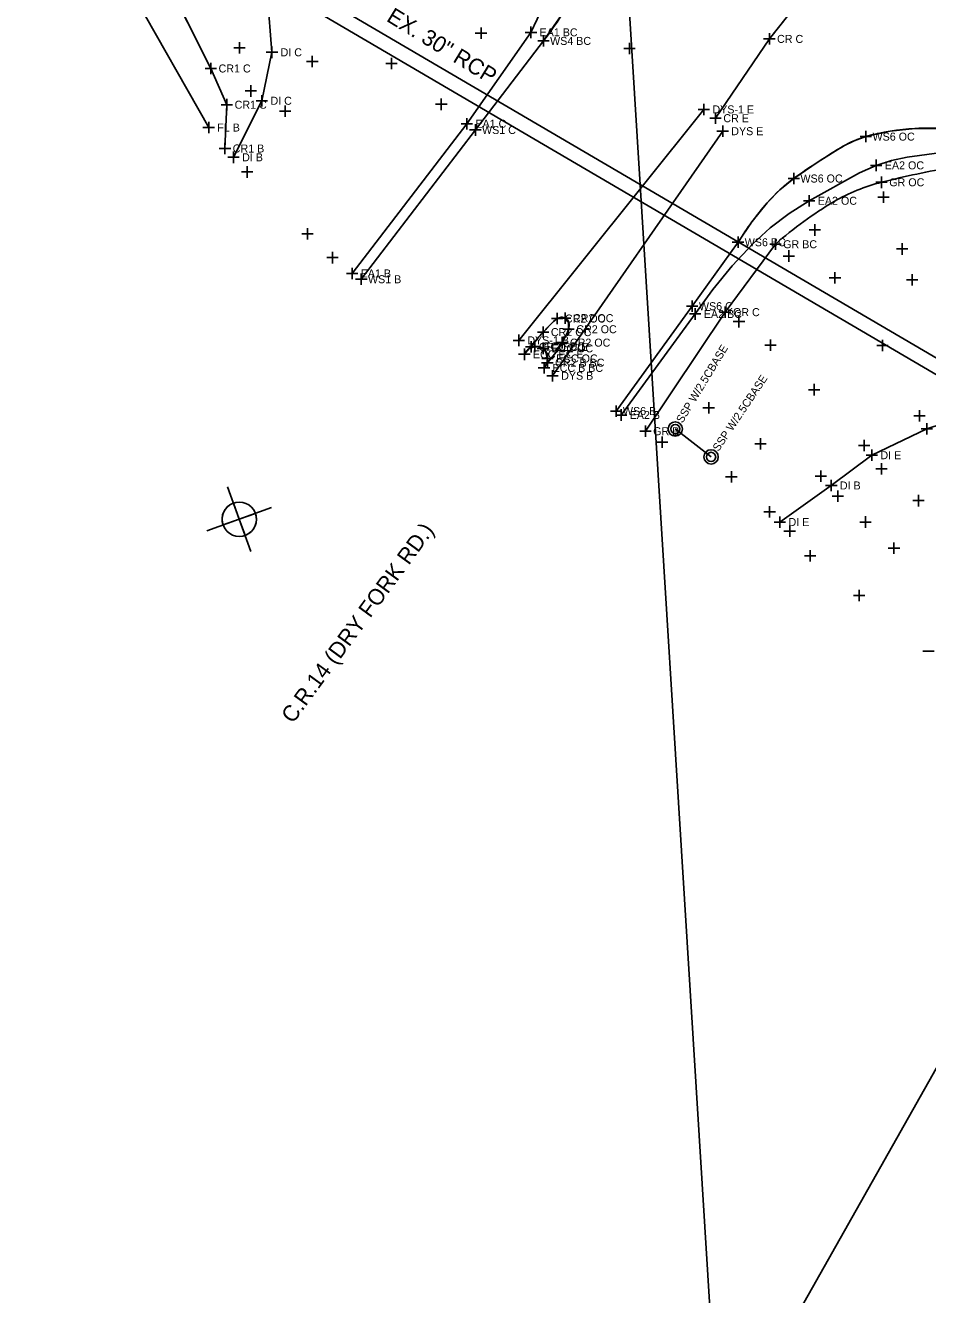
# Model space of a CAD drawing. Extents: x 1324236 to 1326110, y 459090 to 460782.
# Drawn here: x 1324868.3 to 1325026.2, y 459650.5 to 459872.5 of the extents above; entities that cross this region are included whole.
import ezdxf

# ---------------------------------------------------------------- set-up
doc = ezdxf.new("R2010")
doc.units = 0
for name, color, linetype in [('BD_X_Canopy', 7, 'Continuous'), ('DR_X_Ditch', 7, 'Continuous'), ('DR_X_Drive_Pipe', 7, 'Continuous'), ('DR_X_Storm_Sewer', 7, 'Continuous'), ('DT_X_Contour_Minor', 7, 'Continuous'), ('DT_X_Island', 7, 'Continuous'), ('DV_X_Property_Line', 7, 'Continuous'), ('E-RW-ODOT', 7, 'Continuous'), ('GT_Project_Soil_Boring', 7, 'Continuous'), ('PM_X_CL_Double_Solid', 7, 'Continuous'), ('PM_X_Edge_Line', 7, 'Continuous'), ('PM_X_Misc', 7, 'Continuous'), ('PV_X_Shoulder', 7, 'Continuous'), ('RD_X_Text', 7, 'Continuous'), ('RW_X_CL', 7, 'Continuous'), ('RW_X_Esmt_SH', 7, 'Continuous'), ('SN_X_Foundation', 7, 'Continuous'), ('UT_X_Telecom', 7, 'Continuous'), ('VG_X_Flower_Bed', 7, 'Continuous')]:
    doc.layers.add(name, color=color, linetype=linetype)

msp = doc.modelspace()

# ---------------------------------------------------------------- linework, layer by layer
at = {"layer": 'BD_X_Canopy'}
for p, q in [((1324954.64, 459817.45), (1324987.02, 459857.85)), ((1324960.56, 459811.26), (1324990.32, 459854.04))]:
    msp.add_line(p, q, dxfattribs=at)
for points in [[(1325033.14, 459916.69), (1325022.37, 459901.78), (1325012.02, 459887.28), (1324998.48, 459870.18), (1324989.07, 459856.31)], [(1324959.64, 459813.54), (1324961.13, 459815.33), (1324961.13, 459815.33), (1324962.23, 459817.05), (1324962.23, 459817.05), (1324963.09, 459818.72), (1324963.09, 459818.72), (1324963.35, 459819.39), (1324963.35, 459819.39), (1324963.37, 459820.62), (1324963.37, 459820.62), (1324962.77, 459821.33), (1324962.77, 459821.33), (1324962.03, 459821.49), (1324962.03, 459821.49), (1324961.36, 459821.26), (1324961.36, 459821.26), (1324960.74, 459820.75), (1324960.74, 459820.75), (1324958.9, 459818.89), (1324958.9, 459818.89), (1324957.91, 459817.75), (1324957.91, 459817.75), (1324956.8, 459816.3), (1324956.8, 459816.3)]]:
    msp.add_lwpolyline(points, dxfattribs=at)
at = {"layer": 'DR_X_Ditch'}
for points in [[(1324927.09, 459828.14), (1324947.05, 459854.25), (1324958.95, 459869.83), (1324962.07, 459874.27), (1324964.69, 459879.02), (1324964.69, 459879.02), (1324966.48, 459883.2), (1324967.88, 459887.52), (1324968.88, 459891.96), (1324968.88, 459891.96)], [(1324971.69, 459805.08), (1324984.99, 459823.42), (1324993, 459834.61), (1324995.42, 459838.17), (1324998.11, 459841.52), (1324998.11, 459841.52), (1325000.32, 459843.77), (1325002.76, 459845.76), (1325002.76, 459845.76), (1325007.02, 459848.69), (1325011.42, 459851.4), (1325011.42, 459851.4), (1325013.34, 459852.37), (1325015.37, 459853.09), (1325015.37, 459853.09), (1325019.64, 459854.06), (1325023.99, 459854.53), (1325023.99, 459854.53), (1325029.18, 459854.52)], [(1324959.06, 459812.63), (1324959.55, 459813.44), (1324959.55, 459813.44), (1324959.67, 459814.28), (1324959.67, 459814.28), (1324959.4, 459815.4), (1324959.4, 459815.4), (1324958.88, 459816.05), (1324958.88, 459816.05), (1324958.32, 459816.31), (1324958.32, 459816.31), (1324957.45, 459816.38), (1324957.45, 459816.38), (1324956.38, 459815.99), (1324956.38, 459815.99), (1324955.62, 459815.01), (1324955.62, 459815.01)]]:
    msp.add_lwpolyline(points, dxfattribs=at)
for centre, radius, start, end in [((1324964.18, 459817.18), 4.96, 124.6261, 133.9329), ((1324962.1, 459820.19), 1.29, 92.7917, 124.6261), ((1324962.1, 459820.01), 1.48, 63.1066, 92.7917), ((1324962.25, 459820.28), 1.17, 16.6018, 63.1066), ((1324973.77, 459804.91), 20.41, 136.7902, 141.023), ((1324997.15, 459782.96), 52.48, 133.9329, 136.7902), ((1324958.38, 459820.99), 5.22, 334.2458, 342.1532), ((1324961.37, 459820.02), 2.08, 342.1532, 16.6018), ((1324981.13, 459798.96), 29.87, 141.023, 144.5216), ((1324948.72, 459824.47), 15.41, 323.6029, 331.2095), ((1324931.24, 459834.08), 35.36, 331.2095, 334.2458), ((1324945.05, 459827.18), 19.97, 316.922, 323.6029)]:
    msp.add_arc(centre, radius, start, end, dxfattribs=at)
at = {"layer": 'DR_X_Drive_Pipe'}
for p, q in [((1324911.46, 459867.84), (1324910.65, 459878.08)), ((1324909.7, 459859.36), (1324911.46, 459867.84)), ((1324904.74, 459849.47), (1324909.7, 459859.36)), ((1325034.32, 459804.68), (1325026.02, 459801.97)), ((1325026.02, 459801.97), (1325016.41, 459797.36)), ((1325016.41, 459797.36), (1325009.32, 459792.06)), ((1325009.32, 459792.06), (1325000.33, 459785.66))]:
    msp.add_line(p, q, dxfattribs=at)
at = {"layer": 'DR_X_Storm_Sewer'}
for p, q in [((1324954.64, 459817.45), (1324987.02, 459857.85)), ((1324960.56, 459811.26), (1324990.32, 459854.04))]:
    msp.add_line(p, q, dxfattribs=at)
at = {"layer": 'DT_X_Contour_Minor'}
msp.add_line((1324982.02, 459801.95), (1324988.29, 459797.06), dxfattribs=at)
for centre in [(1324982.02, 459801.95), (1324988.29, 459797.06)]:
    msp.add_circle(centre, 0.8, dxfattribs=at)
at = {"layer": 'DT_X_Island'}
for p, q in [((1325012.02, 459887.28), (1324998.48, 459870.18)), ((1324900.76, 459865.01), (1324892.6, 459881.25)), ((1324998.48, 459870.18), (1324989.07, 459856.31)), ((1324903.57, 459858.67), (1324900.76, 459865.01)), ((1324903.24, 459851.01), (1324903.57, 459858.67))]:
    msp.add_line(p, q, dxfattribs=at)
msp.add_lwpolyline([(1324903.24, 459851.01), (1324903.57, 459858.67), (1324900.76, 459865.01), (1324892.6, 459881.25), (1324884.84, 459894.47), (1324875.27, 459911.41), (1324865.42, 459926.97), (1324851.91, 459949.8), (1324844.34, 459963.96), (1324828.37, 459990.29), (1324813.52, 460017.04), (1324795.99, 460045.7), (1324776.37, 460074.14), (1324759.04, 460097.56), (1324741.91, 460121.91), (1324723.89, 460144.49), (1324705.48, 460167.97), (1324684.34, 460188.18), (1324670.72, 460214.69), (1324651.5, 460238.08), (1324632.66, 460258.86), (1324612.54, 460278.22)], dxfattribs=at)
at = {"layer": 'DV_X_Property_Line'}
for p, q in [((1324956.78, 459870.33), (1324956.78, 459872.33)), ((1324955.78, 459871.33), (1324957.78, 459871.33)), ((1324944.55, 459855.34), (1324946.55, 459855.34)), ((1324945.55, 459854.34), (1324945.55, 459856.34)), ((1325016.18, 459848.06), (1325018.18, 459848.06)), ((1325017.18, 459847.06), (1325017.18, 459849.06)), ((1325004.45, 459841.87), (1325006.45, 459841.87)), ((1325005.45, 459840.87), (1325005.45, 459842.87)), ((1324925.49, 459828.15), (1324925.49, 459830.15)), ((1324924.49, 459829.15), (1324926.49, 459829.15)), ((1324984.52, 459822.06), (1324986.52, 459822.06)), ((1324985.52, 459821.06), (1324985.52, 459823.06)), ((1324957.45, 459815.38), (1324957.45, 459817.38)), ((1324958.88, 459815.05), (1324958.88, 459817.05)), ((1324954.62, 459815.01), (1324956.62, 459815.01)), ((1324955.62, 459814.01), (1324955.62, 459816.01)), ((1324956.45, 459816.38), (1324958.45, 459816.38)), ((1324957.88, 459816.05), (1324959.88, 459816.05)), ((1324959.67, 459813.28), (1324959.67, 459815.28)), ((1324958.06, 459812.63), (1324960.06, 459812.63)), ((1324958.67, 459814.28), (1324960.67, 459814.28)), ((1324959.06, 459811.63), (1324959.06, 459813.63)), ((1324971.54, 459804.39), (1324973.54, 459804.39)), ((1324972.54, 459803.39), (1324972.54, 459805.39))]:
    msp.add_line(p, q, dxfattribs=at)
for centre in [(1324982.02, 459801.95), (1324988.29, 459797.06)]:
    msp.add_circle(centre, 1.25, dxfattribs=at)
for centre, radius, start, end in [((1324957.78, 459814.13), 2.33, 126.9602, 157.8828), ((1324957.56, 459814.42), 1.96, 93.2286, 126.9602), ((1324957.62, 459813.32), 3.06, 76.838, 93.2286), ((1324957.98, 459814.85), 1.5, 53.3002, 76.838), ((1324957.88, 459814.72), 1.66, 24.2708, 53.3002), ((1324956.47, 459814.08), 3.21, 3.5121, 24.2708), ((1324957.12, 459814.34), 2.59, 318.6278, 339.7188), ((1324957.63, 459814.15), 2.04, 339.7188, 3.5121)]:
    msp.add_arc(centre, radius, start, end, dxfattribs=at)
at = {"layer": 'E-RW-ODOT'}
for p, q in [((1324989.68, 459622.77), (1324967.69, 459977.08)), ((1324989.68, 459622.77), (1324967.69, 459977.08)), ((1325119.34, 459852.69), (1324989.68, 459622.77))]:
    msp.add_line(p, q, dxfattribs=at)
at = {"layer": 'GT_Project_Soil_Boring'}
for p, q in [((1324905.74, 459786.16), (1324903.71, 459791.81)), ((1324904.73, 459788.99), (1324905.74, 459786.16)), ((1324905.74, 459786.16), (1324911.39, 459788.19)), ((1324905.74, 459786.16), (1324900.09, 459784.14)), ((1324905.74, 459786.16), (1324902.91, 459785.15)), ((1324905.74, 459786.16), (1324908.56, 459787.18)), ((1324905.74, 459786.16), (1324907.76, 459780.51)), ((1324906.75, 459783.34), (1324905.74, 459786.16))]:
    msp.add_line(p, q, dxfattribs=at)
msp.add_circle((1324905.74, 459786.16), 3, dxfattribs=at)
for start, end in [(109.7344, 199.7344), (289.7344, 19.7344)]:
    msp.add_arc((1324905.74, 459786.16), 3, start, end, dxfattribs=at)
at = {"layer": 'PM_X_CL_Double_Solid'}
msp.add_line((1324900.39, 459854.68), (1324887.39, 459877.62), dxfattribs=at)
at = {"layer": 'PM_X_Edge_Line'}
for p, q in [((1324947.05, 459854.25), (1324958.95, 459869.83)), ((1324927.09, 459828.14), (1324947.05, 459854.25)), ((1324984.99, 459823.42), (1324993, 459834.61)), ((1324971.69, 459805.08), (1324984.99, 459823.42))]:
    msp.add_line(p, q, dxfattribs=at)
for centre, radius, start, end in [((1324919.7, 459900.73), 49.95, 321.7901, 334.235), ((1325025.8, 459817.1), 37.47, 92.769, 106.1642), ((1325026.54, 459801.82), 52.77, 81.4885, 92.769), ((1325020.26, 459836.2), 17.59, 106.1642, 120.1668), ((1325062.86, 459762.92), 102.35, 120.1668, 125.9597), ((1325019.22, 459823.06), 28.04, 125.9597, 138.8315), ((1325037.58, 459807.01), 52.42, 138.8315, 148.2369)]:
    msp.add_arc(centre, radius, start, end, dxfattribs=at)
at = {"layer": 'PM_X_Misc'}
for p, q in [((1324990.77, 459822.38), (1324999.54, 459834.26)), ((1324976.8, 459801.55), (1324990.77, 459822.38))]:
    msp.add_line(p, q, dxfattribs=at)
for centre, radius, start, end in [((1325064.42, 459660.73), 190.1, 100.2725, 104.1003), ((1325025.86, 459814.21), 31.86, 104.1003, 120.2848), ((1325041.9, 459786.75), 63.65, 120.2848, 131.7154)]:
    msp.add_arc(centre, radius, start, end, dxfattribs=at)
at = {"layer": 'PV_X_Shoulder'}
for points in [[(1324925.49, 459829.15), (1324945.55, 459855.34), (1324956.78, 459871.33), (1324958.97, 459875.95), (1324960.87, 459880.7), (1324960.87, 459880.7), (1324962.58, 459885.86), (1324963.96, 459891.11), (1324963.96, 459891.11), (1324983.54, 459896), (1324987.7, 459905.44), (1325002.15, 459921.48), (1325006.99, 459922.03), (1325011.69, 459923.28), (1325011.69, 459923.28), (1325015.28, 459924.75), (1325018.67, 459926.62), (1325021.83, 459928.86), (1325021.83, 459928.86), (1325032.72, 459941.95), (1325043.21, 459955.43)], [(1324972.54, 459804.39), (1324985.52, 459822.06), (1324988.59, 459826.37), (1324991.96, 459830.46), (1324995.58, 459834.32), (1324995.58, 459834.32), (1324998.65, 459837.12), (1325001.95, 459839.64), (1325005.45, 459841.87), (1325005.45, 459841.87), (1325014.25, 459846.73), (1325014.25, 459846.73), (1325017.18, 459848.06), (1325017.18, 459848.06), (1325019.85, 459848.92), (1325022.6, 459849.51), (1325022.6, 459849.51), (1325028.21, 459850.26)]]:
    msp.add_lwpolyline(points, dxfattribs=at)
at = {"layer": 'RW_X_CL'}
for p, q in [((1324948.04, 459870.17), (1324948.04, 459872.17)), ((1324947.04, 459871.17), (1324949.04, 459871.17)), ((1324958.95, 459868.83), (1324958.95, 459870.83)), ((1324997.48, 459870.18), (1324999.48, 459870.18)), ((1324998.48, 459869.18), (1324998.48, 459871.18)), ((1324904.8, 459868.64), (1324906.8, 459868.64)), ((1324905.8, 459867.64), (1324905.8, 459869.64)), ((1324957.95, 459869.83), (1324959.95, 459869.83)), ((1324973.03, 459868.5), (1324975.03, 459868.5)), ((1324974.03, 459867.5), (1324974.03, 459869.5)), ((1324900.76, 459864.01), (1324900.76, 459866.01)), ((1324917.52, 459866.24), (1324919.52, 459866.24)), ((1324918.52, 459865.24), (1324918.52, 459867.24)), ((1324931.37, 459865.87), (1324933.37, 459865.87)), ((1324932.37, 459864.87), (1324932.37, 459866.87)), ((1324899.76, 459865.01), (1324901.76, 459865.01)), ((1324906.78, 459861.07), (1324908.78, 459861.07)), ((1324907.78, 459860.07), (1324907.78, 459862.07)), ((1324903.57, 459857.67), (1324903.57, 459859.67)), ((1324941.09, 459857.74), (1324941.09, 459859.74)), ((1324987.02, 459856.85), (1324987.02, 459858.85)), ((1324902.57, 459858.67), (1324904.57, 459858.67)), ((1324912.77, 459857.53), (1324914.77, 459857.53)), ((1324913.77, 459856.53), (1324913.77, 459858.53)), ((1324940.09, 459858.74), (1324942.09, 459858.74)), ((1324986.02, 459857.85), (1324988.02, 459857.85)), ((1324989.07, 459855.31), (1324989.07, 459857.31)), ((1324947.05, 459853.25), (1324947.05, 459855.25)), ((1324988.07, 459856.31), (1324990.07, 459856.31)), ((1324990.32, 459853.04), (1324990.32, 459855.04)), ((1324946.05, 459854.25), (1324948.05, 459854.25)), ((1324989.32, 459854.04), (1324991.32, 459854.04)), ((1325014.37, 459853.09), (1325016.37, 459853.09)), ((1325015.37, 459852.09), (1325015.37, 459854.09)), ((1324902.24, 459851.01), (1324904.24, 459851.01)), ((1324903.24, 459850.01), (1324903.24, 459852.01)), ((1324907.12, 459845.9), (1324907.12, 459847.9)), ((1324906.12, 459846.91), (1324908.12, 459846.91)), ((1325001.76, 459845.76), (1325003.76, 459845.76)), ((1325002.76, 459844.76), (1325002.76, 459846.76)), ((1325018.44, 459841.5), (1325018.44, 459843.5)), ((1325017.44, 459842.5), (1325019.44, 459842.5)), ((1324917.69, 459835.08), (1324917.69, 459837.08)), ((1325005.44, 459836.76), (1325007.44, 459836.76)), ((1325006.44, 459835.76), (1325006.44, 459837.76)), ((1324916.69, 459836.07), (1324918.69, 459836.07)), ((1324992, 459834.61), (1324994, 459834.61)), ((1324993, 459833.61), (1324993, 459835.61)), ((1325021.73, 459832.43), (1325021.73, 459834.43)), ((1324922.05, 459830.92), (1324922.05, 459832.92)), ((1325000.88, 459832.2), (1325002.88, 459832.2)), ((1325001.88, 459831.2), (1325001.88, 459833.2)), ((1325020.73, 459833.43), (1325022.73, 459833.43)), ((1324921.05, 459831.92), (1324923.05, 459831.92)), ((1324926.09, 459828.14), (1324928.09, 459828.14)), ((1324927.09, 459827.14), (1324927.09, 459829.14)), ((1325008.96, 459828.39), (1325010.96, 459828.39)), ((1325009.96, 459827.39), (1325009.96, 459829.39)), ((1325022.48, 459828.03), (1325024.47, 459828.03)), ((1325023.48, 459827.03), (1325023.48, 459829.03)), ((1324983.99, 459823.42), (1324985.99, 459823.42)), ((1324984.99, 459822.42), (1324984.99, 459824.42)), ((1324960.36, 459821.26), (1324962.36, 459821.26)), ((1324961.36, 459820.26), (1324961.36, 459822.26)), ((1324961.77, 459821.33), (1324963.77, 459821.33)), ((1324962.77, 459820.33), (1324962.77, 459822.33)), ((1324993.17, 459819.72), (1324993.17, 459821.72)), ((1324957.9, 459818.89), (1324959.9, 459818.89)), ((1324958.9, 459817.89), (1324958.9, 459819.89)), ((1324962.35, 459819.39), (1324964.35, 459819.39)), ((1324963.35, 459818.39), (1324963.35, 459820.39)), ((1324992.17, 459820.72), (1324994.17, 459820.72)), ((1324953.64, 459817.45), (1324955.64, 459817.45)), ((1324954.64, 459816.45), (1324954.64, 459818.45)), ((1324956.8, 459815.3), (1324956.8, 459817.3)), ((1324961.23, 459817.05), (1324963.23, 459817.05)), ((1324962.23, 459816.05), (1324962.23, 459818.05)), ((1324997.7, 459816.62), (1324999.7, 459816.62)), ((1324998.7, 459815.62), (1324998.7, 459817.62)), ((1325018.29, 459815.56), (1325018.29, 459817.56)), ((1324955.8, 459816.3), (1324957.8, 459816.3)), ((1324959.64, 459812.54), (1324959.64, 459814.54)), ((1325017.29, 459816.56), (1325019.29, 459816.56)), ((1324958.64, 459813.54), (1324960.64, 459813.54)), ((1324960.56, 459810.26), (1324960.56, 459812.26)), ((1324959.56, 459811.26), (1324961.56, 459811.26)), ((1325005.32, 459808.82), (1325007.32, 459808.82)), ((1325006.32, 459807.82), (1325006.32, 459809.82)), ((1324971.69, 459804.08), (1324971.69, 459806.08)), ((1324986.87, 459805.63), (1324988.87, 459805.63)), ((1324987.87, 459804.63), (1324987.87, 459806.63)), ((1324970.69, 459805.08), (1324972.69, 459805.08)), ((1325023.76, 459804.23), (1325025.76, 459804.23)), ((1325024.76, 459803.23), (1325024.76, 459805.23)), ((1324978.73, 459799.64), (1324980.73, 459799.64)), ((1324979.73, 459798.64), (1324979.73, 459800.64)), ((1324995.94, 459799.34), (1324997.94, 459799.34)), ((1324996.94, 459798.34), (1324996.94, 459800.34)), ((1325014.08, 459799.07), (1325016.08, 459799.07)), ((1325015.08, 459798.07), (1325015.08, 459800.07)), ((1324991.83, 459792.57), (1324991.83, 459794.57)), ((1325007.49, 459792.67), (1325007.49, 459794.67)), ((1325017.11, 459794.99), (1325019.11, 459794.99)), ((1325018.11, 459793.99), (1325018.11, 459795.99)), ((1324990.83, 459793.57), (1324992.83, 459793.57)), ((1325006.48, 459793.67), (1325008.49, 459793.67)), ((1325009.46, 459790.2), (1325011.45, 459790.2)), ((1325010.46, 459789.2), (1325010.46, 459791.2)), ((1325024.59, 459788.41), (1325024.59, 459790.41)), ((1324998.53, 459786.46), (1324998.53, 459788.46)), ((1325023.59, 459789.41), (1325025.59, 459789.41)), ((1324997.53, 459787.47), (1324999.53, 459787.47)), ((1325014.3, 459785.67), (1325016.3, 459785.67)), ((1325015.3, 459784.67), (1325015.3, 459786.67)), ((1325001.04, 459784.08), (1325003.04, 459784.08)), ((1325002.04, 459783.08), (1325002.04, 459785.08)), ((1325019.28, 459781.08), (1325021.28, 459781.08)), ((1325020.28, 459780.08), (1325020.28, 459782.08)), ((1325004.62, 459779.74), (1325006.62, 459779.74)), ((1325005.62, 459778.74), (1325005.62, 459780.74)), ((1325013.21, 459772.83), (1325015.21, 459772.83)), ((1325014.21, 459771.83), (1325014.21, 459773.83))]:
    msp.add_line(p, q, dxfattribs=at)
at = {"layer": 'RW_X_Esmt_SH'}
for p, q in [((1324910.46, 459867.84), (1324912.47, 459867.84)), ((1324911.46, 459866.84), (1324911.46, 459868.84)), ((1324908.7, 459859.36), (1324910.7, 459859.36)), ((1324909.7, 459858.36), (1324909.7, 459860.36)), ((1324899.39, 459854.68), (1324901.39, 459854.68)), ((1324900.39, 459853.68), (1324900.39, 459855.68)), ((1324904.74, 459848.47), (1324904.74, 459850.47)), ((1324903.74, 459849.47), (1324905.74, 459849.47)), ((1325018.1, 459844.1), (1325018.1, 459846.1)), ((1325017.1, 459845.1), (1325019.1, 459845.1)), ((1324999.54, 459833.26), (1324999.54, 459835.26)), ((1324998.54, 459834.26), (1325000.54, 459834.26)), ((1324990.77, 459821.38), (1324990.77, 459823.38)), ((1324989.77, 459822.38), (1324991.77, 459822.38)), ((1324975.8, 459801.55), (1324977.8, 459801.55)), ((1324976.8, 459800.55), (1324976.8, 459802.55)), ((1325025.02, 459801.97), (1325027.02, 459801.97)), ((1325026.02, 459800.97), (1325026.02, 459802.97)), ((1325015.41, 459797.36), (1325017.41, 459797.36)), ((1325016.41, 459796.36), (1325016.41, 459798.36)), ((1325009.32, 459791.06), (1325009.32, 459793.06)), ((1325008.32, 459792.06), (1325010.32, 459792.06)), ((1324999.33, 459785.66), (1325001.33, 459785.66)), ((1325000.33, 459784.66), (1325000.33, 459786.66)), ((1325025.34, 459763.05), (1325027.34, 459763.05))]:
    msp.add_line(p, q, dxfattribs=at)
at = {"layer": 'SN_X_Foundation'}
for centre in [(1324982.02, 459801.95), (1324988.29, 459797.06)]:
    msp.add_circle(centre, 1.25, dxfattribs=at)
at = {"layer": 'VG_X_Flower_Bed'}
for p, q in [((1324916.01, 459879.81), (1325034.53, 459810.31)), ((1324914.75, 459877.65), (1325033.27, 459808.16))]:
    msp.add_line(p, q, dxfattribs=at)

# ---------------------------------------------------------------- texts
at = {"layer": 'DT_X_Contour_Minor'}
for rotation, p in [(58.7832, (1324983.28, 459802.87)), (56.1871, (1324989.6, 459797.92))]:
    msp.add_text('SSP W/2.5CBASE', height=1.4, rotation=rotation, dxfattribs=at).set_placement(p)
at = {"layer": 'DV_X_Property_Line'}
for s, p in [('EA1 BC', (1324958.28, 459870.63)), ('EA1 C', (1324947.05, 459854.64)), ('EA2 OC', (1325018.68, 459847.36)), ('EA2 OC', (1325006.95, 459841.17)), ('EA1 B', (1324926.99, 459828.45)), ('EA2 BC', (1324987.02, 459821.36)), ('ECC OC', (1324958.95, 459815.68)), ('ECC OC', (1324960.38, 459815.35)), ('ECC EC E', (1324957.12, 459814.31)), ('ECC OC', (1324961.17, 459813.58)), ('ECC B BC', (1324960.56, 459811.93)), ('EA2 B', (1324974.04, 459803.69))]:
    msp.add_text(s, height=1.4, dxfattribs=at).set_placement(p)
at = {"layer": 'RD_X_Text'}
msp.add_text('C.R.14 (DRY FORK RD.)', height=2.8, rotation=53.8245, dxfattribs=at).set_placement((1324915.13, 459750.28))
at = {"layer": 'RW_X_CL'}
for s, p in [('WS4 BC', (1324960.12, 459869.13)), ('CR C', (1324999.83, 459869.48)), ('CR1 C', (1324902.12, 459864.31)), ('CR1 C', (1324904.93, 459857.97)), ('DYS-1 E', (1324988.52, 459857.15)), ('CR E', (1324990.43, 459855.61)), ('WS1 C', (1324948.21, 459853.55)), ('DYS E', (1324991.82, 459853.34)), ('WS6 OC', (1325016.53, 459852.39)), ('CR1 B', (1324904.6, 459850.31)), ('WS6 OC', (1325003.92, 459845.06)), ('WS6 BC', (1324994.17, 459833.91)), ('WS1 B', (1324928.26, 459827.44)), ('WS6 C', (1324986.16, 459822.72)), ('CR2 OC', (1324962.72, 459820.56)), ('CR2 OC', (1324964.13, 459820.63)), ('CR2 OC', (1324960.26, 459818.19)), ('CR2 OC', (1324964.71, 459818.69)), ('DYS-1 B', (1324956.14, 459816.75)), ('CR2 EC E', (1324958.16, 459815.6)), ('CR2 OC', (1324963.59, 459816.35)), ('CR2 B BC', (1324961, 459812.84)), ('DYS B', (1324962.06, 459810.56)), ('WS6 B', (1324972.86, 459804.38))]:
    msp.add_text(s, height=1.4, dxfattribs=at).set_placement(p)
at = {"layer": 'RW_X_Esmt_SH'}
for s, p in [('DI C', (1324912.97, 459867.14)), ('DI C', (1324911.2, 459858.66)), ('FL B', (1324901.89, 459853.98)), ('DI B', (1324906.24, 459848.77)), ('GR OC', (1325019.46, 459844.4)), ('GR BC', (1325000.9, 459833.56)), ('GR C', (1324992.12, 459821.68)), ('GR B', (1324978.16, 459800.85)), ('DI E', (1325017.91, 459796.66)), ('DI B', (1325010.82, 459791.36)), ('DI E', (1325001.83, 459784.96))]:
    msp.add_text(s, height=1.4, dxfattribs=at).set_placement(p)
at = {"layer": 'UT_X_Telecom'}
msp.add_text('EX. 30" RCP', height=2.8, rotation=328.542, dxfattribs=at).set_placement((1324931.33, 459873.4))

doc.saveas('drawing.dxf')
